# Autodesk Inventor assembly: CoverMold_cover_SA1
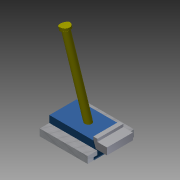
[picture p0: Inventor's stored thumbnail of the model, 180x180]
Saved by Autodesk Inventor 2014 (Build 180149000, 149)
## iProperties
Created: 2009-12
Part Number: CoverMold_cover_SA1
Document SubType Name: Assembly
Designer: gaom
Author: gaom
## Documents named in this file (6)
- C:\Users\iTools\Desktop\tutorial files\Mold\CoverMold\Cover Mold\Sliders\GENERIC_Generic Single Locking 1 1\CoverMold_cover_SA1.iam
- C:\Users\iTools\Desktop\tutorial files\Mold\CoverMold\Cover Mold\Sliders\GENERIC_Generic Single Locking 1 1\CoverMold_cover_SA1_Generic1 Angle Pin.ipt
- C:\Users\iTools\Desktop\tutorial files\Mold\CoverMold\Cover Mold\Sliders\GENERIC_Generic Single Locking 1 1\CoverMold_cover_SA1_Generic1 Locking Heel.ipt
- C:\Users\iTools\Desktop\tutorial files\Mold\CoverMold\Cover Mold\Sliders\GENERIC_Generic Single Locking 1 1\CoverMold_cover_SA1_Generic1 Guide Strip.ipt
- C:\Users\iTools\Desktop\tutorial files\Mold\CoverMold\Cover Mold\Sliders\GENERIC_Generic Single Locking 1 1\CoverMold_cover_SA1_Generic1 Slider.ipt
- C:\Users\iTools\Desktop\tutorial files\Mold\CoverMold\Cover Mold\Sliders\GENERIC_Generic Single Locking 1 1\CoverMold_cover_SA1_Generic1 Guide Strip_1.ipt
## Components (5 placed, 5 different names)
1. CoverMold_cover_SA1_Generic1 Angle Pin:1 — Flush:23, Mate:5
2. CoverMold_cover_SA1_Generic1 Locking Heel:1 — Flush:24, Flush:25, Tangent:1
3. CoverMold_cover_SA1_Generic1 Guide Strip:1 — Flush:23, Flush:25, Flush:26, Flush:27, Mate:6, Flush:30, Flush:31, Flush:32, Flush:33
4. CoverMold_cover_SA1_Generic1 Slider:1 — Mate:5, Tangent:1, Mate:6, Flush:28, Flush:29, Flush:30
5. CoverMold_cover_SA1_Generic1 Guide Strip_1:1 — Flush:31, Flush:32, Flush:33
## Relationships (14: Flush 11, Mate 2, Tangent 1)
- Flush:23: CoverMold_cover_SA1_Generic1 Angle Pin:1 ↔ CoverMold_cover_SA1_Generic1 Guide Strip:1
- Mate:5: CoverMold_cover_SA1_Generic1 Angle Pin:1 ↔ CoverMold_cover_SA1_Generic1 Slider:1
- Flush:24: CoverMold_cover_SA1_Generic1 Locking Heel:1
- Flush:25: CoverMold_cover_SA1_Generic1 Locking Heel:1 ↔ CoverMold_cover_SA1_Generic1 Guide Strip:1
- Tangent:1: CoverMold_cover_SA1_Generic1 Locking Heel:1 ↔ CoverMold_cover_SA1_Generic1 Slider:1
- Flush:26: CoverMold_cover_SA1_Generic1 Guide Strip:1
- Flush:27: CoverMold_cover_SA1_Generic1 Guide Strip:1
- Mate:6: CoverMold_cover_SA1_Generic1 Guide Strip:1 ↔ CoverMold_cover_SA1_Generic1 Slider:1
- Flush:28: CoverMold_cover_SA1_Generic1 Slider:1
- Flush:29: CoverMold_cover_SA1_Generic1 Slider:1
- Flush:30: CoverMold_cover_SA1_Generic1 Guide Strip:1 ↔ CoverMold_cover_SA1_Generic1 Slider:1
- Flush:31: CoverMold_cover_SA1_Generic1 Guide Strip:1 ↔ CoverMold_cover_SA1_Generic1 Guide Strip_1:1
- Flush:32: CoverMold_cover_SA1_Generic1 Guide Strip:1 ↔ CoverMold_cover_SA1_Generic1 Guide Strip_1:1
- Flush:33: CoverMold_cover_SA1_Generic1 Guide Strip:1 ↔ CoverMold_cover_SA1_Generic1 Guide Strip_1:1
